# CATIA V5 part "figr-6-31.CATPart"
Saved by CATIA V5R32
Part number: Part1
Bounding box of the stored display mesh (mm): x -150 to 0, y -70 to 60, z -20 to 40
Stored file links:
  D:\PROJECTS\Project 2022\CATIA V5 6R 2022\Resources\Part Files\c06_catia_v5_6r2022_prt\figr-6-31.CATPart
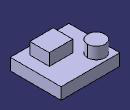
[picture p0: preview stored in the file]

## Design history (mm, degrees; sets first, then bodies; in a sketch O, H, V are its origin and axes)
Body1 (main body)
  Sketch1 on yz-plane, origin (0, 0, 0), H (0, 1, 0), V (0, 0, 1)
    line L1 (-70, 10) -> (60, 10)
    line L2 (60, 10) -> (60, -20)
    line L3 (60, -20) -> (-70, -20)
    line L4 (-70, -20) -> (-70, 10)
    horizontal: L1 H, L3 H
    vertical: L2 V, L4 V
  Pad1: profile Sketch1, direction (-1, 0, 0), length 150
  Sketch2 on face of Pad1 from Sketch1.L1, origin (0, 0, 10), H (1, 0, 0), V (0, 1, 0)
    circle A1 centre (-120, 30) radius 22.3607
  Pad2: profile Sketch2, direction (0, 0, 1), length 30
  Sketch3 on face of Pad1 from Sketch1.L1, origin (0, 0, 10), H (1, 0, 0), V (0, 1, 0)
    point P1 (-90, 0)
    line L1 (-90, 0) -> (-30, 0)
    line L2 (-30, 0) -> (-30, -50)
    line L3 (-30, -50) -> (-90, -50)
    line L4 (-90, -50) -> (-90, 0)
    coincidence: P1 H
    horizontal: L1 H, L3 H
    vertical: L2 V, L4 V
  Pad3: profile Sketch3, direction (0, 0, 1), length 30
